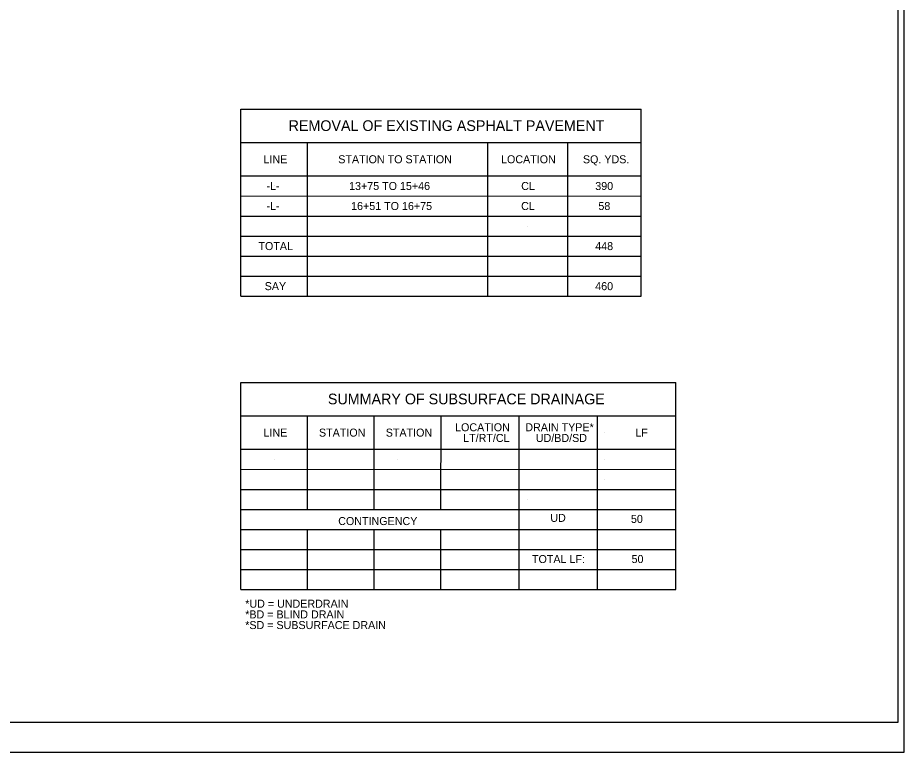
# Model space of a CAD drawing. Extents: x 578158 to 582505, y -54320 to -53220.
# Drawn here: x 579178 to 579842, y -54320 to -53770 of the extents above; entities that cross this region are included whole.
import ezdxf

# ---------------------------------------------------------------- set-up
doc = ezdxf.new("R2010")
doc.units = 0
for name, color, linetype in [('Level 40', 7, 'Continuous'), ('Old_Level_44', 7, 'Continuous'), ('Old_Level_60', 7, 'Continuous'), ('Sheet Plot Border Inside CELL', 7, 'Continuous'), ('Sheet Plot Border Outside CELL', 7, 'Continuous')]:
    doc.layers.add(name, color=color, linetype=linetype)

msp = doc.modelspace()

# ---------------------------------------------------------------- linework, layer by layer
at = {"layer": 'Level 40'}
for p, q in [((579344.8, -53978.08), (579344.81, -53838.08)), ((579344.81, -53838.08), (579644.81, -53838.1)), ((579644.8, -53978.1), (579644.81, -53838.1)), ((579344.81, -53863.08), (579644.81, -53863.1)), ((579394.8, -53978.08), (579394.81, -53863.08)), ((579529.8, -53978.09), (579529.81, -53863.09)), ((579589.8, -53978.1), (579589.81, -53863.1)), ((579344.81, -53888.08), (579644.81, -53888.1)), ((579344.81, -53903.08), (579644.81, -53903.1)), ((579344.81, -53918.08), (579644.81, -53918.1)), ((579344.8, -53933.08), (579644.8, -53933.1)), ((579344.8, -53948.08), (579644.8, -53948.1)), ((579344.8, -53963.08), (579644.8, -53963.1)), ((579344.8, -53978.08), (579644.8, -53978.1)), ((579344.8, -54197.75), (579344.81, -54042.75)), ((579344.81, -54042.75), (579670.72, -54042.77)), ((579670.71, -54197.77), (579670.72, -54042.77)), ((579344.81, -54067.75), (579670.72, -54067.77)), ((579394.8, -54137.75), (579394.81, -54067.75)), ((579444.8, -54137.76), (579444.81, -54067.76)), ((579494.8, -54137.76), (579494.81, -54067.76)), ((579553.44, -54197.76), (579553.44, -54067.76)), ((579612.07, -54197.77), (579612.08, -54067.77)), ((579344.81, -54092.75), (579670.71, -54092.77)), ((579344.81, -54107.75), (579670.71, -54107.77)), ((579344.81, -54122.75), (579670.71, -54122.77)), ((579344.8, -54137.75), (579670.71, -54137.77)), ((579344.8, -54152.75), (579670.71, -54152.77)), ((579394.8, -54197.75), (579394.8, -54152.75)), ((579444.8, -54197.76), (579444.8, -54152.76)), ((579494.8, -54197.76), (579494.8, -54152.76)), ((579344.8, -54167.75), (579670.71, -54167.77)), ((579344.8, -54182.75), (579670.71, -54182.77)), ((579344.8, -54197.75), (579670.71, -54197.77))]:
    msp.add_line(p, q, dxfattribs=at)
at = {"layer": 'Old_Level_60'}
for p, q in [((579369.81, -53875.58), (579369.81, -53875.58)), ((579462.31, -53875.59), (579462.31, -53875.59)), ((579559.81, -53875.59), (579559.81, -53875.59)), ((579617.31, -53875.6), (579617.31, -53875.6)), ((579369.81, -53895.58), (579369.81, -53895.58)), ((579462.31, -53895.59), (579462.31, -53895.59)), ((579559.81, -53895.59), (579559.81, -53895.59)), ((579617.31, -53895.6), (579617.31, -53895.6)), ((579617.31, -53910.6), (579617.31, -53910.6)), ((579559.8, -53925.59), (579559.8, -53925.59)), ((579369.81, -54080.25), (579369.81, -54080.25)), ((579462.31, -54080.26), (579462.31, -54080.26)), ((579617.31, -54080.27), (579617.31, -54080.27)), ((579369.81, -54100.25), (579369.81, -54100.25)), ((579462.31, -54100.26), (579462.31, -54100.26)), ((579617.31, -54100.27), (579617.31, -54100.27)), ((579617.31, -54115.27), (579617.31, -54115.27)), ((579559.8, -54130.26), (579559.8, -54130.26))]:
    msp.add_line(p, q, dxfattribs=at)
at = {"layer": 'Sheet Plot Border Inside CELL'}
msp.add_lwpolyline([(578171.44, -54297.11), (579837.44, -54297.11), (579837.44, -53242.11), (578171.44, -53242.11)], close=True, dxfattribs=at)
at = {"layer": 'Sheet Plot Border Outside CELL'}
msp.add_lwpolyline([(578158.44, -54319.61), (579841.94, -54319.61), (579841.94, -53219.61), (578158.44, -53219.61)], close=True, dxfattribs=at)

# ---------------------------------------------------------------- texts
at = {"layer": 'Old_Level_44'}
for s, height, p in [('REMOVAL OF EXISTING ASPHALT PAVEMENT', 8, (579380.64, -53854.4)), ('LINE', 6, (579361.8, -53878.58)), ('STATION TO STATION', 6, (579417.82, -53878.58)), ('LOCATION', 6, (579539.8, -53878.59)), ('SQ. YDS.', 6, (579601.15, -53878.6)), ('-L-', 6, (579364.03, -53898.58)), ('13+75 TO 15+46', 6, (579425.93, -53898.58)), ('CL', 6, (579554.89, -53898.59)), ('390', 6, (579610.39, -53898.6)), ('-L-', 6, (579363.99, -53913.58)), ('16+51 TO 16+75', 6, (579427.43, -53913.59)), ('CL', 6, (579554.85, -53913.59)), ('58', 6, (579612.74, -53913.6)), ('TOTAL', 6, (579358, -53943.58)), ('448', 6, (579610.37, -53943.6)), ('SAY', 6, (579362.7, -53973.58)), ('460', 6, (579610.36, -53973.6)), ('SUMMARY OF SUBSURFACE DRAINAGE', 8, (579410.08, -54059.07)), ('LOCATION', 6, (579505.37, -54079.26)), ('DRAIN TYPE*', 6, (579557.98, -54079.26)), ('LINE', 6, (579361.8, -54083.25)), ('STATION', 6, (579403.37, -54083.26)), ('STATION', 6, (579453.41, -54083.26)), ('LF', 6, (579640.41, -54083.27)), ('LT/RT/CL', 6, (579511.41, -54087.26)), ('UD/BD/SD', 6, (579565.86, -54087.26)), ('CONTINGENCY', 6, (579417.79, -54149.49)), ('UD', 6, (579576.71, -54147.09)), ('50', 6, (579637.15, -54147.89)), ('TOTAL LF:', 6, (579562.99, -54177.93)), ('50', 6, (579637.58, -54177.93)), ('*UD = UNDERDRAIN', 6, (579348.1, -54211.37)), ('*BD = BLIND DRAIN', 6, (579348.1, -54219.37)), ('*SD = SUBSURFACE DRAIN', 6, (579348.1, -54227.37))]:
    msp.add_text(s, height=height, rotation=359.99585, dxfattribs=at).set_placement(p)

doc.saveas('drawing.dxf')
